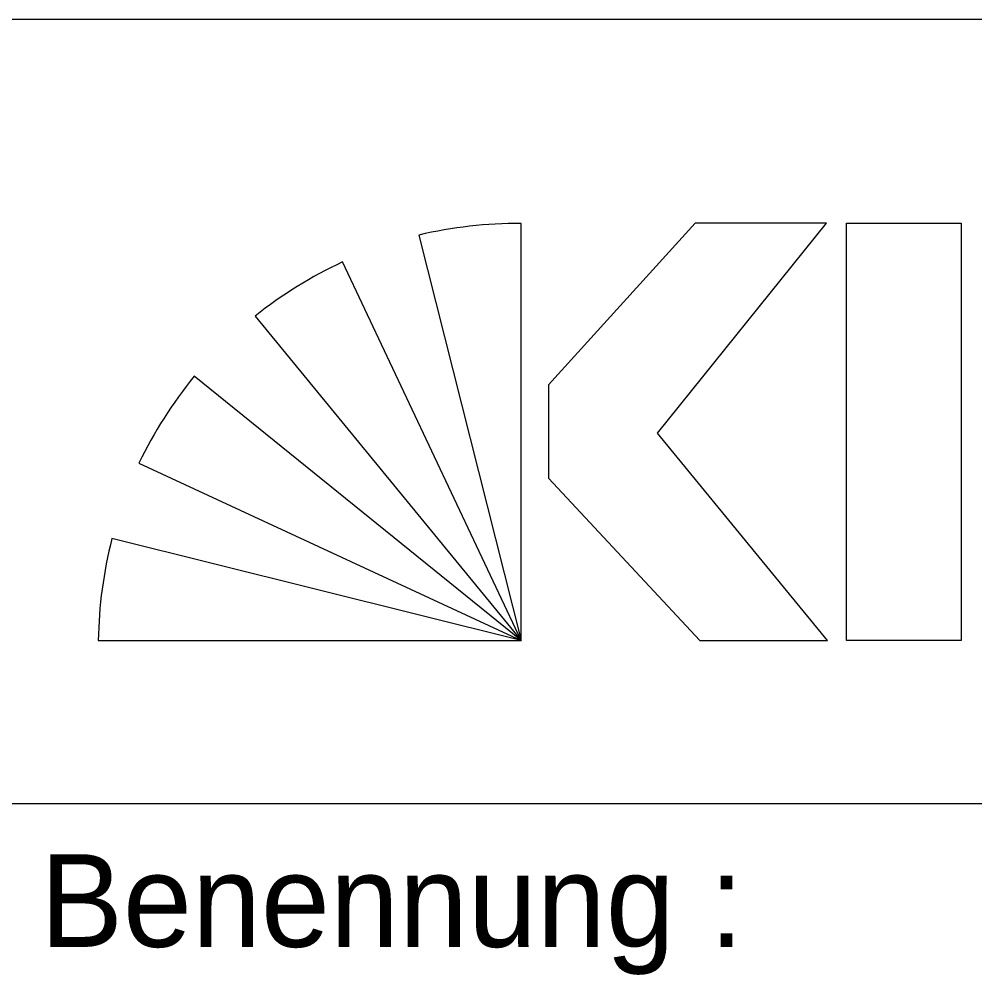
# Model space of a CAD drawing. Extents: x 0 to 119, y 0 to 84.
# Drawn here: x 110.066 to 112.127, y 3.938 to 5.999 of the extents above; entities that cross this region are included whole.
import ezdxf

# ---------------------------------------------------------------- set-up
doc = ezdxf.new("R2010")
doc.units = 0
doc.layers.add('90_Plankopf', color=7, linetype='Continuous')

msp = doc.modelspace()

# ---------------------------------------------------------------- linework, layer by layer
at = {"layer": '90_Plankopf'}
for p, q in [((100.612, 5.999), (118.4, 5.999)), ((100.612, 5.999), (118.4, 5.999)), ((100.612, 5.999), (118.4, 5.999)), ((100.612, 5.999), (118.4, 5.999)), ((111.1481, 4.6586), (111.1481, 5.5584)), ((111.1481, 4.6586), (111.1481, 5.5584)), ((110.9275, 5.5333), (111.1481, 4.6586)), ((110.9275, 5.5333), (111.1481, 4.6586)), ((111.1481, 4.6586), (110.7633, 5.4752)), ((111.1481, 4.6586), (110.7633, 5.4752)), ((110.5744, 5.3585), (111.1481, 4.6586)), ((110.5744, 5.3585), (111.1481, 4.6586)), ((111.1481, 4.6586), (110.4434, 5.2286)), ((111.1481, 4.6586), (110.4434, 5.2286)), ((110.324, 5.0413), (111.1481, 4.6586)), ((110.324, 5.0413), (111.1481, 4.6586)), ((111.1481, 4.6586), (110.2658, 4.8788)), ((111.1481, 4.6586), (110.2658, 4.8788)), ((110.2364, 4.6586), (111.1481, 4.6586)), ((110.2364, 4.6586), (111.1481, 4.6586)), ((110.0001, 4.307), (118.4, 4.307)), ((110.0001, 4.307), (118.4, 4.307))]:
    msp.add_line(p, q, dxfattribs=at)
for points in [[(111.8066, 5.5586), (111.5236, 5.5586), (111.2073, 5.2099), (111.2073, 5.0092), (111.5338, 4.6586), (111.8085, 4.6586), (111.4422, 5.1063)], [(111.8066, 5.5586), (111.5236, 5.5586), (111.2073, 5.2099), (111.2073, 5.0092), (111.5338, 4.6586), (111.8085, 4.6586), (111.4422, 5.1063)], [(112.097, 5.5586), (112.097, 4.6586), (111.8501, 4.6586), (111.8501, 5.5586)], [(112.097, 5.5586), (112.097, 4.6586), (111.8501, 4.6586), (111.8501, 5.5586)]]:
    msp.add_lwpolyline(points, close=True, dxfattribs=at)
for centre, start, end in [((111.1449, 4.6056), 89.8053, 103.1895), ((111.1449, 4.6056), 89.8053, 103.1895), ((111.1662, 4.6118), 115.0126, 128.3968), ((111.1662, 4.6118), 115.0126, 128.3968), ((111.1816, 4.6263), 140.7898, 154.174), ((111.1816, 4.6263), 140.7898, 154.174), ((111.1891, 4.6438), 165.7222, 179.1064), ((111.1891, 4.6438), 165.7222, 179.1064)]:
    msp.add_arc(centre, 0.9528, start, end, dxfattribs=at)

# ---------------------------------------------------------------- texts
msp.add_text('Benennung :', height=0.2, dxfattribs=at).set_placement((110.1113, 3.9979))
msp.add_text('Benennung :', height=0.2, dxfattribs=at).set_placement((110.1113, 3.9979))

doc.saveas('drawing.dxf')
